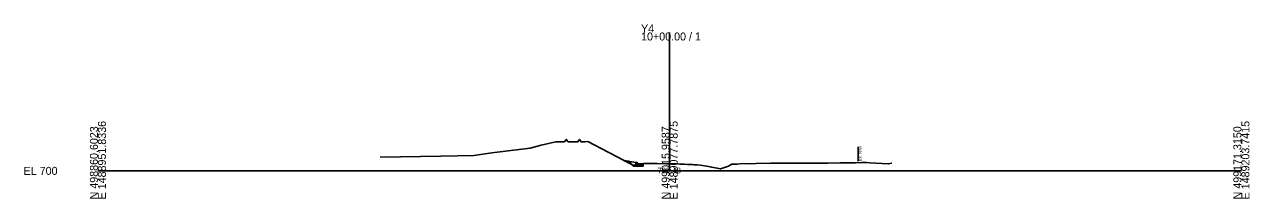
# Model space of a CAD drawing. Extents: x -26 to 1489054, y -10 to 499098.
# Drawn here: x -25.7 to 402.8, y -9.7 to 51.3 of the extents above; entities that cross this region are included whole.
import ezdxf

# ---------------------------------------------------------------- set-up
doc = ezdxf.new("R2010")
doc.units = 0
for name, color, linetype in [('Exist Cross Section Cell', 7, 'Continuous'), ('Exist XS Center Line Elevation Label', 7, 'Continuous'), ('Exist XS Ground Line', 7, 'Continuous'), ('Prop CMT Conc Surface', 7, 'Continuous'), ('Prop CMT Concrete Structures', 7, 'Continuous'), ('Prop CMT Pvmt Course 1 CG', 7, 'Continuous'), ('Prop CMT Slope Grass', 7, 'Continuous'), ('Prop CMT Subgrade Earthwork', 7, 'Continuous'), ('Prop XS Earthwork Shape', 7, 'Continuous'), ('Scratch_Level_1', 7, 'Continuous'), ('Scratch_Level_4', 7, 'Continuous')]:
    doc.layers.add(name, color=color, linetype=linetype)

msp = doc.modelspace()

# ---------------------------------------------------------------- linework, layer by layer
at = {"layer": 'Exist Cross Section Cell'}
for p, q in [((200, 0), (200, 48.46)), ((0, 0), (200, 0)), ((200, 0), (400, 0))]:
    msp.add_line(p, q, dxfattribs=at)
at = {"layer": 'Exist XS Ground Line'}
msp.add_lwpolyline([(98.77, 4.75), (119.95, 5.15), (131.46, 5.36), (137.74, 6.29), (151.23, 7.98), (155.09, 8.96), (160.14, 10.13), (161.58, 10.13), (163.2, 10.16), (163.82, 11), (164.46, 10.18), (166.46, 10.18), (167.91, 10.2), (168.47, 11.01), (169, 10.21), (170.35, 10.21), (171.4, 10.23), (186.35, 2.41), (187.14, 1.99), (189.32, 2.32), (190.2, 2.49), (190.7, 2.53), (191.38, 2.55), (192, 2.55), (192.33, 2.55), (193.78, 2.56), (195.57, 2.55), (198.77, 2.5), (199.11, 2.49), (199.98, 2.48), (200.64, 2.46), (201.98, 2.42), (202.67, 2.4), (203.51, 2.37), (204.45, 2.34), (205.2, 2.3), (206.22, 2.26), (207.48, 2.2), (208, 2.17), (208.42, 2.15), (209.3, 2.11), (209.67, 2.09), (210.73, 2.01), (212.13, 1.78), (213.56, 1.58), (214.72, 1.29), (217.77, 0.69), (220.58, 1.67), (221.8, 2.29), (223.57, 2.38), (225.36, 2.53), (228.32, 2.51), (230.21, 2.54), (235.31, 2.7), (238.5, 2.66), (255.35, 2.71), (259.61, 2.77), (262.16, 2.78), (262.81, 2.79), (263.19, 2.8), (265.02, 2.86), (267.19, 2.89), (268.87, 2.92), (269.97, 2.83), (276.44, 2.41), (277.72, 2.64)], dxfattribs=at)
at = {"layer": 'Prop CMT Conc Surface'}
for points in [[(188.7, 2.46), (188.69, 2.96), (188.19, 2.96)], [(190.7, 2.53), (188.7, 2.46)]]:
    msp.add_lwpolyline(points, dxfattribs=at)
at = {"layer": 'Prop CMT Concrete Structures'}
for points in [[(190.7, 2.53), (188.7, 2.46), (188.69, 2.96), (188.19, 2.96)], [(188.19, 2.96), (188.2, 1.96), (190.7, 1.95)], [(190.7, 1.95), (190.7, 2.53)]]:
    msp.add_lwpolyline(points, dxfattribs=at)
at = {"layer": 'Prop CMT Pvmt Course 1 CG'}
for points in [[(190.7, 1.95), (187.7, 1.97), (187.41, 1.68)], [(187.41, 1.68), (190.7, 1.66)], [(190.7, 1.66), (190.7, 1.95)]]:
    msp.add_lwpolyline(points, dxfattribs=at)
at = {"layer": 'Prop CMT Slope Grass'}
msp.add_line((188.19, 2.96), (183.93, 3.67), dxfattribs=at)
at = {"layer": 'Prop CMT Subgrade Earthwork'}
msp.add_line((190.7, 1.66), (190.7, 2.53), dxfattribs=at)
msp.add_lwpolyline([(190.7, 1.66), (187.41, 1.68), (185.7, 3.38)], dxfattribs=at)
at = {"layer": 'Prop XS Earthwork Shape'}
for points in [[(185.7, 3.38), (183.93, 3.67), (186.35, 2.41), (187.04, 2.04)], [(190.7, 1.66), (190.7, 2.53), (190.2, 2.49), (189.32, 2.32), (187.14, 1.99), (187.04, 2.04), (187.41, 1.68)]]:
    msp.add_lwpolyline(points, close=True, dxfattribs=at)
at = {"layer": 'Scratch_Level_4'}
msp.add_line((266, 8.38), (266, 3.38), dxfattribs=at)

# ---------------------------------------------------------------- texts
at = {"layer": 'Exist Cross Section Cell'}
for s, p in [('Y4', (190, 48.46)), ('10+00.00 / 1', (190, 45.66)), ('EL 700', (-26, -1.4))]:
    msp.add_text(s, height=2.8, dxfattribs=at).set_placement(p)
for s, p in [('E 1488951.8336', (2.8, -10)), ('E 1489077.7875', (202.8, -10)), ('E 1489203.7415', (402.8, -10)), ('N 498860.6023', (0, -10)), ('N 499015.9587', (200, -10)), ('N 499171.3150', (400, -10))]:
    msp.add_text(s, height=2.8, rotation=90, dxfattribs=at).set_placement(p)
at = {"layer": 'Exist XS Center Line Elevation Label'}
msp.add_text('702.48', height=2, dxfattribs=at).set_placement((195.74, -0.87))
at = {"layer": 'Scratch_Level_1'}
for s, p in [('LT_Sub_OEOP', (187.31, 1.67)), ('LT_CG1_Shelf_Out', (187.56, 1.96)), ('LT_CG_Top_BOC', (188.08, 2.95)), ('LT_CG_Bot_BOC', (188.08, 1.95)), ('LT_CG_Top_Face', (188.57, 2.95)), ('LT_CG_Top_Gut', (188.58, 2.45))]:
    msp.add_text(s, height=0.02, dxfattribs=at).set_placement(p)
at = {"layer": 'Scratch_Level_4'}
msp.add_text('EX. R/W', height=1, rotation=90, dxfattribs=at).set_placement((267.2, 3.38))

doc.saveas('drawing.dxf')
